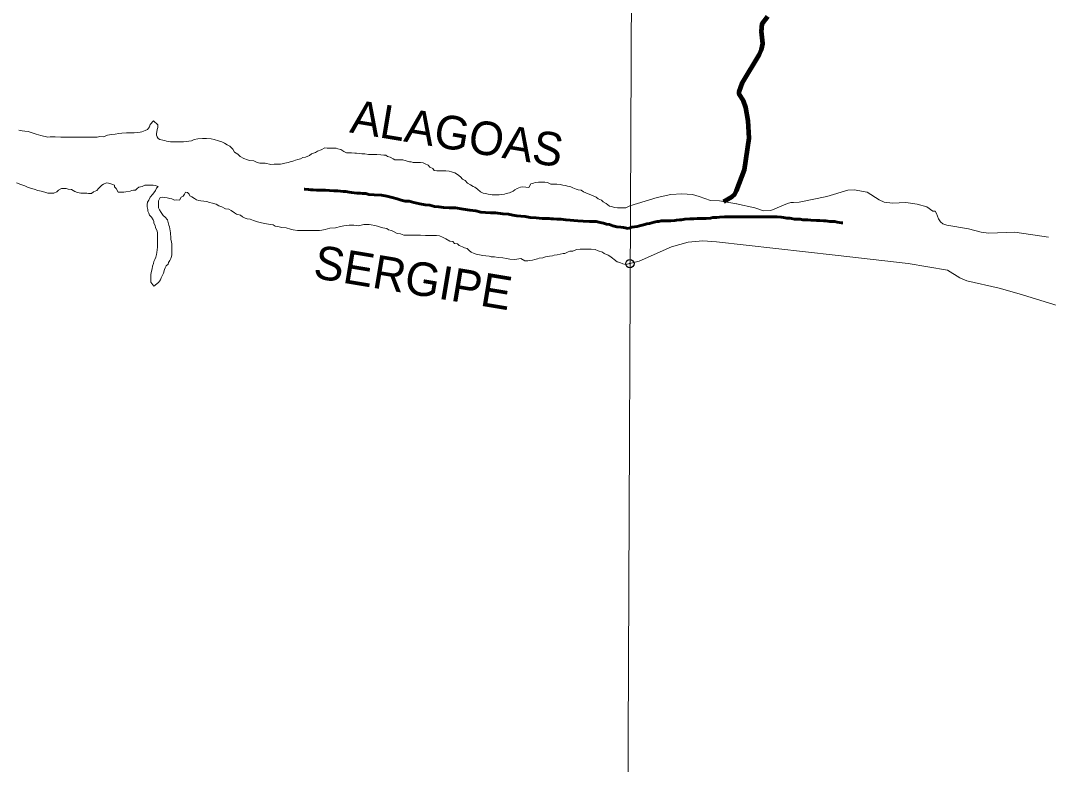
# Model space of a CAD drawing. Extents: x -1643653 to 4543381, y 1624270 to 13878484.
# Drawn here: x 657253 to 669530, y 8915829 to 8924721 of the extents above; entities that cross this region are included whole.
import ezdxf
from ezdxf.enums import TextEntityAlignment as Align

# ---------------------------------------------------------------- set-up
doc = ezdxf.new("R2010")
doc.units = 0
doc.header["$LTSCALE"] = 200
doc.header["$PDMODE"] = 32
doc.header["$PDSIZE"] = 100
doc.linetypes.add('LONG_DASH_SHORT_DASH', pattern=[9.9, 6, -1.2, 1.5, -1.2])
for name, color, linetype, lineweight in [('1', 7, 'Continuous', 13), ('24', 7, 'Continuous', 25), ('25', 7, 'Continuous', 13), ('53', 7, 'Continuous', 106), ('60', 7, 'Continuous', 13), ('7', 7, 'LONG_DASH_SHORT_DASH', 60)]:
    doc.layers.add(name, color=color, linetype=linetype, lineweight=lineweight)
doc.layers.add('42', color=7, linetype='Continuous')

msp = doc.modelspace()

# ---------------------------------------------------------------- linework, layer by layer
at = {"layer": '1'}
msp.add_lwpolyline([(664968.2, 9023436.8), (664657.1, 8949509), (664397.1, 8890880.2)], dxfattribs=at)
at = {"layer": '24'}
for points in [[(665654.1, 8922558.1), (665747.4, 8922613.4), (665782.6, 8922644.9), (665804.2, 8922685), (665898.2, 8922937), (665956.6, 8923316.8), (665944.3, 8923521), (665915.9, 8923680.3), (665887.1, 8923762.6), (665837.8, 8923840.4), (665834.9, 8923868.6), (665876, 8923981.1), (666075.9, 8924311.2), (666104.4, 8924374.8), (666118.2, 8924447.8), (666103.2, 8924589.1), (666111.8, 8924680), (666180.2, 8924767.7)], [(665804.2, 8922685), (665782.6, 8922644.9), (665747.4, 8922613.4), (665654.1, 8922558.1)]]:
    msp.add_lwpolyline(points, dxfattribs=at)
msp.add_point((664531.1, 8921815.4), dxfattribs=at)
at = {"layer": '25'}
for points in [[(657230.3, 8923409.9), (657272.8, 8923404.6), (657302.8, 8923399.4), (657345.2, 8923394.1), (657377.7, 8923381.4), (657437.6, 8923363.5), (657495, 8923348.1), (657577.3, 8923327.5), (657604.9, 8923329.8), (657624.9, 8923329.7), (657664.9, 8923329.4), (657732.4, 8923329), (657805, 8923328.5), (657862.5, 8923328.1), (657887.5, 8923328), (657925, 8923327.7), (657945, 8923327.6), (657992.5, 8923327.3), (658027.5, 8923327), (658082.6, 8923326.7), (658110.1, 8923326.5), (658167.6, 8923326.1), (658197.7, 8923333.4), (658242.7, 8923333.1), (658290.3, 8923352.8), (658337.9, 8923360), (658383, 8923364.7), (658428, 8923369.5), (658460.6, 8923374.2), (658518.2, 8923378.9), (658568.2, 8923378.5), (658610.7, 8923380.8), (658645.7, 8923383), (658680.8, 8923387.8), (658700.8, 8923390.2), (658741, 8923407.4), (658768.6, 8923417.3), (658791.3, 8923452.2), (658801.5, 8923479.6), (658839.4, 8923524.4), (658894.1, 8923476.5), (658893.8, 8923444), (658886.1, 8923419), (658878.4, 8923391.5), (658878.2, 8923371.5), (658878.1, 8923351.4), (658883, 8923331.4), (658895.3, 8923311.3), (658917.7, 8923298.6), (658952.7, 8923290.9), (658975.1, 8923285.7), (658997.6, 8923280.6), (659045.1, 8923272.7), (659075.1, 8923272.5), (659120.1, 8923272.2), (659142.6, 8923272.1), (659177.6, 8923271.9), (659200.1, 8923271.7), (659240.2, 8923273.9), (659262.7, 8923278.8), (659295.3, 8923283.6), (659327.9, 8923300.9), (659370.5, 8923308.1), (659425.5, 8923310.3), (659473.1, 8923310), (659528.1, 8923307.1), (659565.5, 8923299.3), (659617.9, 8923284), (659655.3, 8923271.2), (659690.2, 8923256), (659720.1, 8923235.7), (659752.5, 8923218), (659789.7, 8923185.2), (659807, 8923147.5), (659849.3, 8923124.7), (659876.6, 8923094.5), (659919, 8923074.2), (659963.8, 8923056.4), (659988.8, 8923048.7), (660038.8, 8923043.3), (660078.7, 8923025.6), (660111.1, 8923015.3)], [(660111.1, 8923015.3), (660173.6, 8923017.4), (660243.5, 8922999.4), (660281.1, 8923004.2), (660301.1, 8923004.1), (660323.6, 8923006.4), (660356.1, 8923006.2), (660376.2, 8923008.6), (660411.2, 8923018.4), (660448.8, 8923023.1), (660471.4, 8923030.5), (660493.9, 8923037.8), (660516.5, 8923042.7), (660536.6, 8923052.6), (660564.1, 8923059.9), (660596.7, 8923069.7), (660624.3, 8923084.5), (660656.9, 8923089.3), (660704.6, 8923109.1), (660729.7, 8923126.4), (660774.9, 8923143.6), (660797.5, 8923161), (660842.6, 8923175.7), (660885.3, 8923198), (660915.3, 8923197.8), (660940.3, 8923197.6), (660980.4, 8923197.3), (661020.4, 8923194.6), (661042.8, 8923186.9), (661077.8, 8923181.7), (661115.1, 8923156.4), (661147.5, 8923138.7), (661187.5, 8923138.4), (661207.5, 8923138.3), (661245, 8923138), (661265, 8923137.9), (661305, 8923132.6), (661327.5, 8923130), (661365, 8923127.2), (661407.5, 8923119.4), (661447.5, 8923119.2), (661472.5, 8923119), (661507.5, 8923118.8), (661557.5, 8923115.9), (661592.5, 8923113.2), (661615, 8923110.5), (661637.4, 8923095.4), (661667.3, 8923087.7), (661702.2, 8923067.4), (661724.6, 8923057.2), (661754.6, 8923057), (661819.7, 8923056.6), (661897, 8923033.6), (661919.5, 8923030.9), (661942, 8923025.8), (661972, 8923023.1), (662009.5, 8923022.8), (662029.5, 8923022.7), (662062, 8923019.9), (662086.9, 8923009.8), (662121.8, 8922992), (662141.6, 8922969.4), (662176.5, 8922954.1), (662193.8, 8922928.9), (662226.3, 8922923.7), (662258.8, 8922923.5), (662293.8, 8922923.3), (662313.9, 8922923.2), (662333.9, 8922923), (662371.4, 8922922.8), (662401.3, 8922912.6), (662438.7, 8922899.8), (662471.1, 8922879.6), (662508.4, 8922854.3), (662530.7, 8922824.1), (662563.1, 8922808.8), (662592.9, 8922776.1), (662625.2, 8922758.4), (662657.6, 8922738.1), (662680, 8922728), (662712.4, 8922707.7), (662747.2, 8922674.9), (662777.1, 8922659.7), (662804.5, 8922652), (662839.5, 8922644.3), (662884.5, 8922639), (662917, 8922638.8), (662937, 8922638.6), (662969.5, 8922638.4), (662992, 8922640.8), (663032.1, 8922645.5), (663054.6, 8922652.9), (663094.7, 8922662.6), (663134.9, 8922679.9), (663155, 8922697.3), (663182.6, 8922712.1), (663225.3, 8922729.4), (663250.3, 8922734.2), (663325.3, 8922723.7), (663348.2, 8922771.1), (663378.2, 8922778.4)], [(663378.2, 8922778.4), (663398.3, 8922785.8), (663440.8, 8922790.5), (663478.4, 8922790.3), (663513.3, 8922787.5), (663545.9, 8922787.3), (663588.2, 8922767), (663623.2, 8922764.3), (663658.2, 8922764.1), (663698.2, 8922761.3), (663730.7, 8922753.6), (663760.7, 8922748.3), (663785.6, 8922740.7), (663825.6, 8922735.4), (663850.5, 8922720.2), (663890.4, 8922704.9), (663912.8, 8922697.3), (663950.3, 8922692), (663977.7, 8922674.3), (664032.5, 8922648.9), (664084.9, 8922631), (664127.3, 8922608.2), (664152.1, 8922590.5), (664192, 8922572.8), (664211.9, 8922552.6), (664249.2, 8922534.8), (664286.5, 8922504.5), (664309, 8922496.9), (664348.9, 8922486.6), (664381.4, 8922481.4), (664416.4, 8922481.1), (664436.4, 8922481), (664461.5, 8922483.3), (664481.5, 8922483.2), (664531.1, 8922504.7), (664855.7, 8922606.1), (665018.2, 8922640.1), (665151.9, 8922649.8), (665276.6, 8922642.6), (665359.5, 8922619.8)], [(658100, 8922655.6), (658065, 8922655.8), (658042.5, 8922656), (657999.9, 8922656.3), (657972.4, 8922659), (657932.5, 8922666.7), (657900.1, 8922679.5), (657860.2, 8922702.3), (657820.2, 8922707.5), (657797.8, 8922715.2), (657762.8, 8922715.4), (657742.8, 8922715.6), (657707.6, 8922693.3), (657684.9, 8922673.4), (657649.8, 8922656.1), (657629.8, 8922656.2), (657609.8, 8922656.3), (657577.2, 8922656.6), (657542.3, 8922671.8), (657499.9, 8922682.1), (657460, 8922689.9), (657415.1, 8922707.7), (657382.6, 8922712.9), (657335.2, 8922728.3), (657305.3, 8922746), (657255.4, 8922761.3), (657205.5, 8922781.7)], [(658980.7, 8922371.9), (659008, 8922339.2), (659017.7, 8922306.6), (659025, 8922274), (659032.3, 8922253.9), (659039.5, 8922208.8), (659041.8, 8922183.7), (659044.1, 8922163.7), (659046.5, 8922141.1), (659048.7, 8922108.6), (659055.9, 8922071), (659058.3, 8922050.9), (659058.1, 8922030.9), (659060.5, 8922010.9), (659060.3, 8921988.3), (659060.1, 8921955.8), (659059.8, 8921920.7), (659057.2, 8921900.7), (659047, 8921878.3), (659034.3, 8921853.3), (659021.6, 8921830.9), (659013.9, 8921808.4), (658991.3, 8921791), (658981.1, 8921766), (658970.9, 8921743.6), (658960.6, 8921703.6), (658945.3, 8921668.6), (658932.7, 8921646.2), (658922.5, 8921623.7), (658899.7, 8921591.3), (658844.4, 8921546.6), (658809.7, 8921594.4), (658807.5, 8921627), (658807.6, 8921649.5), (658807.9, 8921684.6), (658815.7, 8921724.6), (658823.4, 8921752.1), (658828.7, 8921787.1), (658838.9, 8921817.1), (658844.1, 8921842.1), (658856.8, 8921864.5), (658869.5, 8921894.5), (658874.8, 8921924.5), (658879.9, 8921947), (658882.7, 8921982), (658887.9, 8922012), (658888.2, 8922042), (658888.3, 8922064.6), (658888.6, 8922097.1), (658888.8, 8922132.2), (658889, 8922152.2), (658889.2, 8922182.2), (658884.4, 8922202.3), (658864.7, 8922247.5), (658859.9, 8922270.1), (658845.1, 8922297.7), (658842.7, 8922317.7), (658835.4, 8922337.8), (658818.1, 8922370.5), (658793.3, 8922393.2), (658786, 8922420.8), (658773.6, 8922440.9), (658771.3, 8922460.9), (658766.5, 8922493.5), (658766.8, 8922523.5), (658767, 8922548.6), (658784.7, 8922576), (658802.4, 8922608.4), (658827.7, 8922640.8), (658845.4, 8922663.2), (658863.1, 8922690.6), (658875.8, 8922718.1), (658896, 8922738), (658861, 8922748.2), (658836, 8922753.4), (658803.5, 8922753.6), (658778.5, 8922753.8), (658738.5, 8922754), (658705.8, 8922736.7), (658665.8, 8922729.5), (658645.6, 8922712.1), (658625.5, 8922694.7), (658603, 8922694.8), (658580.4, 8922690), (658560.4, 8922682.6), (658510.3, 8922675.4), (658485.2, 8922670.6), (658452.7, 8922668.3), (658417.7, 8922671), (658395.5, 8922713.7), (658375.7, 8922733.9), (658373.3, 8922753.9), (658343.4, 8922764.2), (658303.5, 8922779.4), (658281, 8922782.1), (658243.4, 8922767.3), (658223.2, 8922752.4), (658182.9, 8922712.7), (658162.8, 8922690.2), (658122.6, 8922673), (658100, 8922655.6)], [(662255.4, 8922147.4), (662220.4, 8922150.2), (662177.9, 8922153), (662152.9, 8922153.1), (662112.9, 8922153.4), (662087.9, 8922153.6), (662027.9, 8922154), (661975.4, 8922154.3), (661940.3, 8922154.5), (661900.3, 8922154.8), (661872.8, 8922155), (661830.3, 8922155.3), (661790.4, 8922170.6), (661750.4, 8922175.8), (661715.6, 8922196.1), (661683.2, 8922211.3), (661648.2, 8922221.6), (661625.8, 8922236.7), (661578.3, 8922242.1), (661538.5, 8922257.3), (661516, 8922265), (661483.5, 8922270.2), (661441.1, 8922278), (661416.1, 8922283.2), (661373.6, 8922283.5), (661351.1, 8922283.6), (661290.9, 8922269), (661233.5, 8922274.4), (661178.4, 8922274.7), (661150.9, 8922272.4), (661115.8, 8922267.6), (661075.8, 8922260.4), (661015.6, 8922243.3), (660945.6, 8922238.7), (660892.9, 8922224.1), (660852.8, 8922216.8), (660825.3, 8922212), (660772.8, 8922209.8), (660732.7, 8922210.1), (660682.7, 8922210.4), (660637.7, 8922210.7), (660610.2, 8922210.9), (660560.2, 8922211.2), (660510.2, 8922219.1), (660475.2, 8922226.8), (660425.4, 8922244.7), (660375.4, 8922247.5), (660342.9, 8922255.2), (660295.5, 8922263.1), (660268.1, 8922280.8), (660213.1, 8922286.1), (660165.6, 8922294), (660113.2, 8922309.3), (660080.8, 8922317.1), (660035.9, 8922332.4), (659996, 8922347.7), (659958.5, 8922352.9), (659936, 8922360.6), (659903.6, 8922375.8), (659878.8, 8922393.5), (659833.8, 8922408.8), (659809, 8922424), (659766.6, 8922449.3), (659739.3, 8922467), (659699.3, 8922472.3), (659656.9, 8922492.6), (659619.5, 8922505.4), (659587.1, 8922525.6), (659547.2, 8922538.4), (659509.8, 8922546.2), (659477.3, 8922556.4), (659442.3, 8922561.6), (659407.4, 8922566.8), (659382.4, 8922569.5), (659354.9, 8922577.2), (659330, 8922592.4), (659297.7, 8922615.2), (659275.2, 8922625.3), (659267.9, 8922645.4), (659245.6, 8922665.6), (659223.1, 8922668.2), (659210.4, 8922645.8), (659195.2, 8922623.3), (659170.1, 8922611), (659152.3, 8922576.1), (659117.3, 8922576.3), (659092.3, 8922573.9), (659059.9, 8922589.2), (659037.4, 8922594.3), (659002.5, 8922602.1), (658967.5, 8922607.3), (658945, 8922610), (658920, 8922605.1), (658902.2, 8922567.7), (658902, 8922540.2), (658899.2, 8922502.6), (658901.5, 8922482.6), (658913.8, 8922460), (658933.6, 8922427.3), (658955.8, 8922392.1), (658980.7, 8922371.9)], [(665807.2, 8922530.5), (665805.3, 8922529), (666021.2, 8922480.8), (666128.1, 8922448.4), (666212.6, 8922450.2), (666414.1, 8922533.6), (666451.7, 8922544.9), (666486.4, 8922546.2), (666551.6, 8922551.4), (666883.2, 8922619.3), (667134.9, 8922692.2), (667207.8, 8922696.8), (667366, 8922668.8), (667507, 8922579.6), (667567.9, 8922550.4), (667666.3, 8922536.7), (667827.1, 8922544.8), (667960.2, 8922528.3), (668076.2, 8922494.1), (668149.9, 8922444.5), (668175.3, 8922440.9), (668193.4, 8922414.2), (668215.8, 8922353.1), (668240.8, 8922316.8), (668270.3, 8922290.6), (668317.3, 8922273.5), (668576.3, 8922231.4), (668724.7, 8922190.8), (668817.5, 8922180.4), (669130.5, 8922192.7), (669530, 8922132.2)], [(665359.5, 8922619.8), (665492.3, 8922568.3), (665600, 8922565.9), (665805.3, 8922529)], [(663096.2, 8921869), (663056.2, 8921876.8), (663013.8, 8921884.6), (662958.8, 8921889.9), (662913.8, 8921895.2), (662873.8, 8921898), (662851.3, 8921903.2), (662811.4, 8921908.4), (662773.9, 8921913.7), (662733.9, 8921921.5), (662696.5, 8921929.2), (662671.5, 8921936.9), (662634.1, 8921952.2), (662611.8, 8921972.3), (662586.9, 8921997.5), (662557, 8922002.8), (662529.6, 8922017.9), (662492.2, 8922033.2), (662469.8, 8922050.9), (662434.8, 8922056.1), (662415, 8922081.3), (662380, 8922084), (662332.7, 8922111.9), (662292.8, 8922132.2), (662255.4, 8922147.4)], [(670613, 8921062.4), (670594.6, 8921075.1), (670505.7, 8921092.1), (670378.9, 8921097.7), (670172.5, 8921136.1), (669790.2, 8921268), (669181.6, 8921455.5), (668940.4, 8921522.2), (668553.3, 8921609.1), (668470.6, 8921646), (668322.8, 8921739.3), (667855.1, 8921816.8), (666980.9, 8921915.9), (665565.9, 8922078.1), (665402.5, 8922087.8), (665227.8, 8922071.5), (665027.5, 8922015.6), (664640.9, 8921845.5), (664531.1, 8921815.4)], [(664531.1, 8921815.4), (664483.8, 8921807.2), (664446.4, 8921815), (664411.5, 8921827.8), (664379, 8921835.5), (664344.2, 8921863.2), (664321.8, 8921880.9), (664292, 8921903.7), (664269.6, 8921918.8), (664224.7, 8921936.6), (664202.3, 8921954.3), (664152.4, 8921969.7), (664117.5, 8921984.9), (664070, 8921987.7), (664027.5, 8921988), (663982.5, 8921988.3), (663937.5, 8921988.6), (663892.4, 8921983.9), (663849.7, 8921964.2), (663814.7, 8921964.4), (663792.2, 8921957), (663754.5, 8921937.2), (663734.5, 8921937.4), (663696.9, 8921930.1), (663661.8, 8921922.8), (663626.8, 8921915.6), (663606.7, 8921910.7), (663571.7, 8921905.9), (663524.1, 8921898.7), (663491.5, 8921883.9), (663446.4, 8921879.2), (663426.3, 8921871.8), (663396.3, 8921867), (663366.2, 8921857.2), (663333.7, 8921852.4), (663311.1, 8921850.1), (663276.1, 8921850.3), (663226.3, 8921875.7), (663156.2, 8921863.6), (663096.2, 8921869)]]:
    msp.add_lwpolyline(points, dxfattribs=at)
msp.add_point((664531.1, 8921815.4), dxfattribs=at)
at = {"layer": '53'}
msp.add_lwpolyline([(665654.1, 8922558.1), (665747.4, 8922613.4), (665782.6, 8922644.9), (665804.2, 8922685), (665898.2, 8922937), (665956.6, 8923316.8), (665944.3, 8923521), (665915.9, 8923680.3), (665887.1, 8923762.6), (665837.8, 8923840.4), (665834.9, 8923868.6), (665876, 8923981.1), (666075.9, 8924311.2), (666104.4, 8924374.8), (666118.2, 8924447.8), (666103.2, 8924589.1), (666111.8, 8924680), (666180.2, 8924767.7)], dxfattribs=at)
at = {"layer": '60', "lineweight": 25}
msp.add_spline([(814781, 9009175.5), (814787.2, 9009173.4), (814796.9, 9009173.4), (814799.4, 9009172.4), (814805.1, 9009174.5), (814805.6, 9009176.5), (814811.7, 9009179.5), (814811.7, 9009179.5), (814801.5, 9009181), (814790.7, 9009181.5), (814784.1, 9009183.1), (814777.4, 9009185.1), (814778.4, 9009175.5)], degree=3, dxfattribs=at)
at = {"layer": '7'}
for points in [[(663706.2, 8922345.6), (663656.3, 8922348.3), (663616.3, 8922351.1), (663591.3, 8922351.2), (663566.3, 8922353.8), (663526.3, 8922354), (663483.8, 8922356.8), (663411.3, 8922362.1), (663341.4, 8922367.5), (663281.5, 8922380.3), (663226.5, 8922383.1), (663181.5, 8922388.4), (663134.1, 8922393.7), (663081.6, 8922406.4), (663011.7, 8922409.3), (662926.8, 8922422.3), (662864.2, 8922422.6), (662806.8, 8922425.4), (662751.8, 8922430.7), (662691.9, 8922448.5), (662617, 8922453.9), (662539.5, 8922466.8), (662447.1, 8922482.4), (662372.1, 8922482.8), (662304.7, 8922488.1), (662249.7, 8922493.4), (662197.2, 8922498.7), (662142.3, 8922514), (662087.4, 8922516.8), (662020, 8922529.7), (661950.1, 8922547.6), (661892.6, 8922560.4), (661845.2, 8922563.1), (661797.8, 8922575.9), (661750.3, 8922591.1), (661690.5, 8922606.5), (661625.6, 8922621.8), (661563.1, 8922634.7), (661478.2, 8922637.6), (661413.2, 8922643), (661378.3, 8922655.7), (661338.3, 8922655.9), (661310.8, 8922656), (661268.3, 8922658.8), (661238.3, 8922661.4), (661205.8, 8922666.6), (661175.9, 8922669.3), (661135.9, 8922677), (661105.9, 8922679.6), (661076, 8922682.3), (661041, 8922687.5), (660993.5, 8922687.7), (660941, 8922690.5), (660893.5, 8922693.3), (660841, 8922693.6), (660786, 8922693.8), (660746, 8922696.6), (660718.5, 8922696.7), (660691.1, 8922701.8), (660648.6, 8922704.6), (660641.7, 8922706.3)], [(664555.3, 8922251.1), (664510.5, 8922233.7), (664455.6, 8922249), (664420.6, 8922251.7), (664375.7, 8922254.4), (664325.7, 8922267.2), (664288.3, 8922282.4), (664250.9, 8922287.6), (664213.5, 8922300.3), (664176, 8922305.6), (664128.6, 8922318.3), (664086.1, 8922318.5), (664048.6, 8922321.2), (663973.6, 8922324.1), (663908.6, 8922327), (663861.2, 8922332.2), (663816.2, 8922335), (663763.7, 8922340.3), (663706.2, 8922345.6)], [(666977.6, 8922317.6), (666919.1, 8922320.2), (666870.8, 8922327.8), (666842.8, 8922327.8), (666799.5, 8922330.4), (666761.3, 8922330.4), (666692.6, 8922335.5), (666657, 8922338), (666595.9, 8922340.6), (666565.4, 8922345.7), (666519.6, 8922348.3), (666496.7, 8922348.3), (666461.1, 8922355.9), (666440.7, 8922358.5), (666405.1, 8922361), (666366.9, 8922366.2), (666338.9, 8922371.3), (666290.6, 8922376.4), (666227, 8922376.4), (666168.5, 8922376.4), (666140.5, 8922376.4), (666092.1, 8922376.4), (666061.6, 8922376.4), (665980.2, 8922376.4), (665944.5, 8922376.4), (665886, 8922376.4), (665855.5, 8922376.4), (665799.5, 8922376.4), (665769, 8922376.4), (665697.7, 8922376.4), (665659.6, 8922376.4), (665601, 8922371.2), (665570.5, 8922368.7), (665519.6, 8922366.1), (665494.2, 8922361), (665443.3, 8922355.9), (665400, 8922355.9), (665377.1, 8922355.9), (665333.9, 8922355.9), (665293.2, 8922350.8), (665244.8, 8922350.8), (665188.8, 8922348.2), (665145.6, 8922340.6), (665122.7, 8922338), (665087.1, 8922335.5), (665066.7, 8922330.3), (665018.4, 8922327.8), (664987.8, 8922327.8), (664962.4, 8922327.8), (664934.4, 8922327.8), (664903.9, 8922327.8), (664875.9, 8922320.1), (664855.5, 8922320.1), (664819.9, 8922309.9), (664791.9, 8922304.8), (664763.9, 8922297.1), (664733.4, 8922289.4), (664708, 8922281.8), (664677.4, 8922276.7), (664646.9, 8922269), (664616.4, 8922261.3), (664585.8, 8922256.2), (664555.3, 8922251.1), (664555.3, 8922251.1), (664555.3, 8922251.1)], [(667073.5, 8922301.6), (667059.1, 8922304.8), (667005.6, 8922309.9), (666977.6, 8922317.6)]]:
    msp.add_lwpolyline(points, dxfattribs=at)

# ---------------------------------------------------------------- texts
at = {"layer": '42'}
for s, p in [('ALAGOAS', (662435, 8923174.8)), ('SERGIPE', (661908.6, 8921452.5))]:
    msp.add_text(s, height=400, rotation=350.533, dxfattribs=at).set_placement(p, align=Align.CENTER)

doc.saveas('drawing.dxf')
